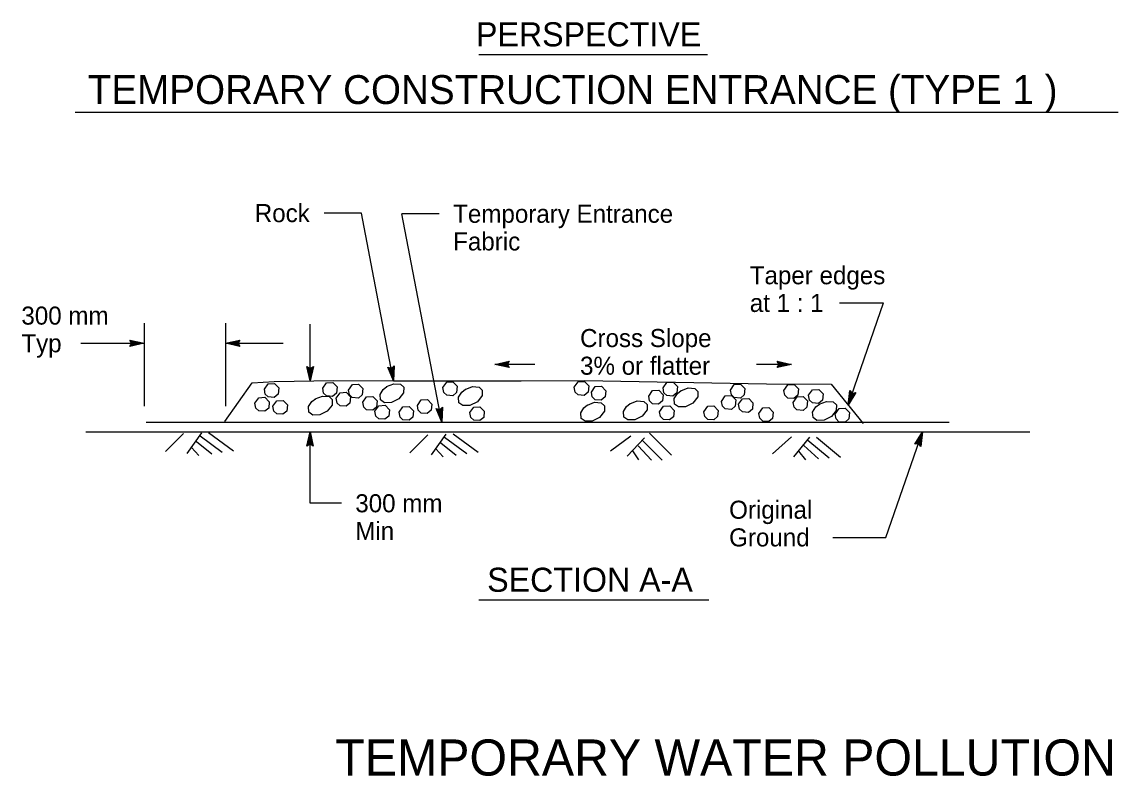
# Model space of a CAD drawing. Extents: x 6707406 to 6714471, y 1868570 to 1872341.
# Drawn here: x 6710442.3 to 6710879.6, y 1869895.8 to 1870196.5 of the extents above; entities that cross this region are included whole.
import ezdxf

# ---------------------------------------------------------------- set-up
doc = ezdxf.new("R2010")
doc.units = 0
for name, color, linetype in [('10 Sheet Formats', 7, 'Continuous'), ('56 Stg 3 Anno', 7, 'Continuous'), ('57 Undefined', 7, 'Continuous'), ('59 Soundwall Ann', 7, 'Continuous'), ('60 Nongeo Data', 7, 'Continuous')]:
    doc.layers.add(name, color=color, linetype=linetype)

msp = doc.modelspace()

# ---------------------------------------------------------------- linework, layer by layer
at = {"layer": '56 Stg 3 Anno'}
for p, q in [((6710577.77, 1870120.29), (6710562.94, 1870120.29)), ((6710590.62, 1870053.41), (6710577.77, 1870120.29)), ((6710609.91, 1870036.94), (6710593.95, 1870120.03)), ((6710608.78, 1870120.03), (6710593.95, 1870120.03)), ((6710768.54, 1870084.46), (6710786.08, 1870084.46)), ((6710771.94, 1870043.7), (6710786.08, 1870084.46)), ((6710491.13, 1870076.42), (6710491.13, 1870043.28)), ((6710523.55, 1870076.42), (6710523.55, 1870043.28)), ((6710557.31, 1870053.34), (6710557.31, 1870076.04)), ((6710465.81, 1870068.37), (6710491.13, 1870068.37)), ((6710486.14, 1870068.37), (6710485.37, 1870069.66)), ((6710485.37, 1870069.66), (6710485.37, 1870069.66)), ((6710485.37, 1870069.66), (6710491.13, 1870068.37)), ((6710491.13, 1870068.37), (6710485.37, 1870067.09)), ((6710485.37, 1870067.09), (6710486.14, 1870068.37)), ((6710485.37, 1870067.09), (6710485.37, 1870067.09)), ((6710485.58, 1870069.31), (6710489.8, 1870068.37)), ((6710489.79, 1870068.37), (6710485.59, 1870067.44)), ((6710488.48, 1870068.37), (6710485.76, 1870067.77)), ((6710485.8, 1870068.97), (6710488.48, 1870068.37)), ((6710485.97, 1870068.64), (6710487.15, 1870068.37)), ((6710487.15, 1870068.37), (6710485.99, 1870068.12)), ((6710491.13, 1870068.37), (6710491.13, 1870068.37)), ((6710523.55, 1870068.37), (6710529.31, 1870069.65)), ((6710523.55, 1870068.37), (6710546.59, 1870068.37)), ((6710529.31, 1870067.08), (6710523.55, 1870068.37)), ((6710523.55, 1870068.37), (6710523.55, 1870068.37)), ((6710529.1, 1870067.42), (6710524.87, 1870068.37)), ((6710524.88, 1870068.37), (6710529.08, 1870069.3)), ((6710526.2, 1870068.37), (6710528.91, 1870068.97)), ((6710528.88, 1870067.77), (6710526.2, 1870068.37)), ((6710527.53, 1870068.37), (6710528.69, 1870068.62)), ((6710528.71, 1870068.1), (6710527.53, 1870068.37)), ((6710529.31, 1870069.65), (6710528.54, 1870068.37)), ((6710528.54, 1870068.37), (6710529.31, 1870067.08)), ((6710529.31, 1870069.65), (6710529.31, 1870069.65)), ((6710529.31, 1870067.08), (6710529.31, 1870067.08)), ((6710557.31, 1870053.34), (6710556.03, 1870059.1)), ((6710556.03, 1870059.1), (6710556.03, 1870059.1)), ((6710556.03, 1870059.1), (6710557.31, 1870058.33)), ((6710557.31, 1870054.68), (6710556.38, 1870058.87)), ((6710557.31, 1870055.99), (6710556.71, 1870058.7)), ((6710557.31, 1870057.32), (6710557.06, 1870058.48)), ((6710557.31, 1870058.33), (6710558.6, 1870059.1)), ((6710558.6, 1870059.1), (6710557.31, 1870053.34)), ((6710558.26, 1870058.89), (6710557.31, 1870054.66)), ((6710557.91, 1870058.67), (6710557.31, 1870055.99)), ((6710557.58, 1870058.5), (6710557.31, 1870057.32)), ((6710558.6, 1870059.1), (6710558.6, 1870059.1)), ((6710590.62, 1870053.41), (6710588.28, 1870058.82)), ((6710588.28, 1870058.82), (6710588.28, 1870058.82)), ((6710588.28, 1870058.82), (6710589.68, 1870058.31)), ((6710590.37, 1870054.72), (6710588.66, 1870058.67)), ((6710590.12, 1870056.01), (6710589.02, 1870058.56)), ((6710589.87, 1870057.31), (6710589.4, 1870058.41)), ((6710589.68, 1870058.31), (6710590.8, 1870059.31)), ((6710589.91, 1870058.52), (6710589.87, 1870057.31)), ((6710590.21, 1870058.75), (6710590.12, 1870056.01)), ((6710590.5, 1870059.04), (6710590.37, 1870054.71)), ((6710590.8, 1870059.31), (6710590.62, 1870053.41)), ((6710590.8, 1870059.31), (6710590.8, 1870059.31)), ((6710631.02, 1870059.97), (6710636.78, 1870061.24)), ((6710646.98, 1870059.97), (6710631.02, 1870059.97)), ((6710636.78, 1870058.68), (6710631.02, 1870059.97)), ((6710631.02, 1870059.97), (6710631.02, 1870059.97)), ((6710636.57, 1870059.02), (6710632.34, 1870059.97)), ((6710632.35, 1870059.97), (6710636.55, 1870060.9)), ((6710633.67, 1870059.96), (6710636.38, 1870060.57)), ((6710636.34, 1870059.37), (6710633.67, 1870059.96)), ((6710634.99, 1870059.96), (6710636.15, 1870060.22)), ((6710636.17, 1870059.7), (6710634.99, 1870059.96)), ((6710636.78, 1870061.24), (6710636.01, 1870059.97)), ((6710636.01, 1870059.97), (6710636.78, 1870058.68)), ((6710636.78, 1870061.24), (6710636.78, 1870061.24)), ((6710636.78, 1870058.68), (6710636.78, 1870058.68)), ((6710749.39, 1870059.97), (6710735.38, 1870059.97)), ((6710744.4, 1870059.97), (6710743.63, 1870061.25)), ((6710743.63, 1870061.25), (6710743.63, 1870061.25)), ((6710743.63, 1870061.25), (6710749.39, 1870059.97)), ((6710749.39, 1870059.97), (6710743.63, 1870058.69)), ((6710743.63, 1870058.69), (6710744.4, 1870059.97)), ((6710743.63, 1870058.69), (6710743.63, 1870058.69)), ((6710743.84, 1870060.91), (6710748.07, 1870059.97)), ((6710748.06, 1870059.96), (6710743.86, 1870059.03)), ((6710746.74, 1870059.97), (6710744.03, 1870059.37)), ((6710744.07, 1870060.57), (6710746.74, 1870059.97)), ((6710744.24, 1870060.23), (6710745.42, 1870059.97)), ((6710745.42, 1870059.97), (6710744.26, 1870059.71)), ((6710749.39, 1870059.97), (6710749.39, 1870059.97)), ((6710557.31, 1870053.34), (6710557.31, 1870053.34)), ((6710590.62, 1870053.41), (6710590.62, 1870053.41)), ((6710771.94, 1870043.7), (6710772.62, 1870049.56)), ((6710775.04, 1870048.72), (6710771.94, 1870043.7)), ((6710772.37, 1870044.96), (6710772.87, 1870049.23)), ((6710774.65, 1870048.63), (6710772.37, 1870044.95)), ((6710772.62, 1870049.56), (6710772.62, 1870049.56)), ((6710772.62, 1870049.56), (6710773.58, 1870048.41)), ((6710772.81, 1870046.2), (6710773.13, 1870048.96)), ((6710774.25, 1870048.53), (6710772.81, 1870046.2)), ((6710773.25, 1870047.45), (6710773.38, 1870048.63)), ((6710773.88, 1870048.48), (6710773.25, 1870047.45)), ((6710773.58, 1870048.41), (6710775.04, 1870048.72)), ((6710775.04, 1870048.72), (6710775.04, 1870048.72)), ((6710609.91, 1870036.94), (6710607.57, 1870042.35)), ((6710607.57, 1870042.35), (6710607.57, 1870042.35)), ((6710607.57, 1870042.35), (6710608.97, 1870041.84)), ((6710609.66, 1870038.25), (6710607.96, 1870042.2)), ((6710609.42, 1870039.54), (6710608.31, 1870042.09)), ((6710609.17, 1870040.84), (6710608.7, 1870041.93)), ((6710608.97, 1870041.84), (6710610.09, 1870042.84)), ((6710609.2, 1870042.05), (6710609.17, 1870040.84)), ((6710609.5, 1870042.28), (6710609.42, 1870039.54)), ((6710609.8, 1870042.57), (6710609.67, 1870038.24)), ((6710610.09, 1870042.84), (6710609.91, 1870036.94)), ((6710610.09, 1870042.84), (6710610.09, 1870042.84)), ((6710771.94, 1870043.7), (6710771.94, 1870043.7)), ((6710609.91, 1870036.94), (6710609.91, 1870036.94)), ((6710556.03, 1870027.33), (6710557.31, 1870033.09)), ((6710556.37, 1870027.54), (6710557.31, 1870031.77)), ((6710557.31, 1870004.56), (6710557.31, 1870033.09)), ((6710557.31, 1870033.09), (6710557.31, 1870033.09)), ((6710557.31, 1870033.09), (6710558.59, 1870027.33)), ((6710557.31, 1870031.76), (6710558.24, 1870027.56)), ((6710787.05, 1869990.95), (6710801.67, 1870033.11)), ((6710798.57, 1870028.09), (6710801.67, 1870033.11)), ((6710798.96, 1870028.17), (6710801.24, 1870031.86)), ((6710801.24, 1870031.84), (6710800.74, 1870027.57)), ((6710801.67, 1870033.11), (6710800.99, 1870027.25)), ((6710801.67, 1870033.11), (6710801.67, 1870033.11)), ((6710557.31, 1870028.1), (6710556.03, 1870027.33)), ((6710556.03, 1870027.33), (6710556.03, 1870027.33)), ((6710556.71, 1870027.77), (6710557.31, 1870030.44)), ((6710557.04, 1870027.93), (6710557.31, 1870029.11)), ((6710557.31, 1870030.44), (6710557.91, 1870027.73)), ((6710557.31, 1870029.11), (6710557.57, 1870027.95)), ((6710558.59, 1870027.33), (6710557.31, 1870028.1)), ((6710558.59, 1870027.33), (6710558.59, 1870027.33)), ((6710800.04, 1870028.39), (6710798.57, 1870028.09)), ((6710798.57, 1870028.09), (6710798.57, 1870028.09)), ((6710799.36, 1870028.27), (6710800.8, 1870030.6)), ((6710799.73, 1870028.32), (6710800.37, 1870029.35)), ((6710800.99, 1870027.25), (6710800.04, 1870028.39)), ((6710800.37, 1870029.35), (6710800.23, 1870028.17)), ((6710800.8, 1870030.6), (6710800.48, 1870027.84)), ((6710800.99, 1870027.25), (6710800.99, 1870027.25)), ((6710569.84, 1870004.56), (6710557.31, 1870004.56)), ((6710765.86, 1869990.95), (6710787.05, 1869990.95))]:
    msp.add_line(p, q, dxfattribs=at)
at = {"layer": '57 Undefined'}
for p, q in [((6710624.62, 1870183.57), (6710715.9, 1870183.57)), ((6710463.58, 1870160.57), (6710879.64, 1870160.57)), ((6710624.57, 1869966.04), (6710716.36, 1869966.04))]:
    msp.add_line(p, q, dxfattribs=at)
at = {"layer": '59 Soundwall Ann'}
for p, q in [((6710506.78, 1870032.33), (6710499.61, 1870025.22)), ((6710513.93, 1870032.67), (6710508.15, 1870024.43)), ((6710513.39, 1870031.45), (6710522.28, 1870024.9)), ((6710516.84, 1870032.8), (6710526.79, 1870025.47)), ((6710604.29, 1870031.82), (6710597.12, 1870024.7)), ((6710611.44, 1870032.16), (6710605.66, 1870023.91)), ((6710610.89, 1870030.94), (6710619.79, 1870024.39)), ((6710614.34, 1870032.28), (6710624.3, 1870024.96)), ((6710685.24, 1870031.37), (6710677.11, 1870025.37)), ((6710690.68, 1870030.67), (6710683.76, 1870023.35)), ((6710692.73, 1870032.48), (6710701.51, 1870023.78)), ((6710749.31, 1870031), (6710741.73, 1870024.33)), ((6710756.47, 1870030.92), (6710750.21, 1870023.03)), ((6710759.38, 1870030.87), (6710768.87, 1870022.96)), ((6710510.01, 1870026.8), (6710512.91, 1870023.61)), ((6710511.95, 1870029.19), (6710518.05, 1870024.21)), ((6710609.45, 1870028.67), (6710615.56, 1870023.69)), ((6710688.21, 1870027.51), (6710693.52, 1870021.7)), ((6710689.96, 1870029.54), (6710697.81, 1870021.77)), ((6710754.28, 1870027.55), (6710760.08, 1870022.22)), ((6710755.85, 1870029.73), (6710764.34, 1870022.66)), ((6710607.51, 1870026.29), (6710610.42, 1870023.09)), ((6710685.94, 1870025.43), (6710688.35, 1870021.85)), ((6710752.2, 1870025.29), (6710754.91, 1870021.93))]:
    msp.add_line(p, q, dxfattribs=at)
at = {"layer": '60 Nongeo Data'}
for p, q in [((6710491.88, 1870036.94), (6710638.48, 1870036.94)), ((6710638.48, 1870036.94), (6710812.22, 1870036.94)), ((6710467.82, 1870033.11), (6710637.9, 1870033.11)), ((6710637.9, 1870033.11), (6710844.47, 1870033.11))]:
    msp.add_line(p, q, dxfattribs=at)
for points in [[(6710523.29, 1870037.15), (6710534.22, 1870052.61), (6710543, 1870053.06), (6710566.73, 1870053.52), (6710590.57, 1870053.41), (6710641.46, 1870053.45)], [(6710562.32, 1870050.4), (6710563.87, 1870052.6), (6710566.34, 1870052.74), (6710568.06, 1870050.96), (6710567.81, 1870048.46), (6710566.28, 1870047.19), (6710563.84, 1870047.37), (6710562.69, 1870048.48), (6710562.32, 1870050.4)], [(6710610.27, 1870050.67), (6710611.82, 1870052.87), (6710614.3, 1870053.01), (6710616.02, 1870051.23), (6710615.77, 1870048.73), (6710614.24, 1870047.46), (6710611.8, 1870047.64), (6710610.65, 1870048.75), (6710610.27, 1870050.67)], [(6710641.46, 1870053.45), (6710666.79, 1870053.47), (6710739.37, 1870052.21), (6710765.14, 1870052.09), (6710777.89, 1870036.35)], [(6710662.71, 1870050.8), (6710664.26, 1870053), (6710666.73, 1870053.15), (6710668.45, 1870051.36), (6710668.2, 1870048.86), (6710666.68, 1870047.59), (6710664.23, 1870047.77), (6710663.08, 1870048.88), (6710662.71, 1870050.8)], [(6710698.1, 1870050.55), (6710699.65, 1870052.75), (6710702.12, 1870052.89), (6710703.84, 1870051.11), (6710703.59, 1870048.61), (6710702.07, 1870047.34), (6710699.62, 1870047.51), (6710698.47, 1870048.63), (6710698.1, 1870050.55)], [(6710539.06, 1870050.02), (6710540.61, 1870052.23), (6710543.09, 1870052.37), (6710544.8, 1870050.59), (6710544.56, 1870048.08), (6710543.03, 1870046.81), (6710540.58, 1870046.99), (6710539.43, 1870048.11), (6710539.06, 1870050.02)], [(6710567.72, 1870046.47), (6710569.27, 1870048.67), (6710571.75, 1870048.81), (6710573.47, 1870047.03), (6710573.22, 1870044.53), (6710571.69, 1870043.26), (6710569.25, 1870043.44), (6710568.1, 1870044.55), (6710567.73, 1870046.47)], [(6710572.61, 1870049.73), (6710574.16, 1870051.94), (6710576.64, 1870052.08), (6710578.36, 1870050.29), (6710578.11, 1870047.79), (6710576.58, 1870046.52), (6710574.14, 1870046.7), (6710572.99, 1870047.81), (6710572.62, 1870049.73)], [(6710587.83, 1870051.08), (6710590.73, 1870052.23), (6710593.4, 1870052), (6710594.66, 1870050.8), (6710594.62, 1870048.63), (6710592.7, 1870046.18), (6710589.73, 1870044.69), (6710586.93, 1870044.64), (6710585.36, 1870045.76), (6710585.21, 1870047.99), (6710586.48, 1870049.99), (6710587.95, 1870051.15)], [(6710619.17, 1870049.97), (6710622.07, 1870051.12), (6710624.74, 1870050.89), (6710626, 1870049.69), (6710625.96, 1870047.53), (6710624.04, 1870045.07), (6710621.07, 1870043.59), (6710618.27, 1870043.54), (6710616.7, 1870044.66), (6710616.55, 1870046.89), (6710617.83, 1870048.88), (6710619.29, 1870050.05)], [(6710669.5, 1870048.89), (6710671.05, 1870051.09), (6710673.52, 1870051.23), (6710675.24, 1870049.45), (6710674.99, 1870046.95), (6710673.46, 1870045.68), (6710671.02, 1870045.86), (6710669.87, 1870046.97), (6710669.5, 1870048.89)], [(6710692.39, 1870047.28), (6710693.94, 1870049.49), (6710696.42, 1870049.63), (6710698.14, 1870047.85), (6710697.89, 1870045.35), (6710696.36, 1870044.07), (6710693.92, 1870044.25), (6710692.77, 1870045.37), (6710692.4, 1870047.28)], [(6710705.17, 1870049.45), (6710708.07, 1870050.6), (6710710.73, 1870050.37), (6710712, 1870049.16), (6710711.96, 1870047), (6710710.03, 1870044.55), (6710707.06, 1870043.06), (6710704.27, 1870043.01), (6710702.69, 1870044.13), (6710702.54, 1870046.36), (6710703.82, 1870048.36), (6710705.28, 1870049.52)], [(6710724.99, 1870049.73), (6710726.54, 1870051.94), (6710729.01, 1870052.08), (6710730.73, 1870050.29), (6710730.48, 1870047.79), (6710728.95, 1870046.52), (6710726.51, 1870046.7), (6710725.36, 1870047.81), (6710724.99, 1870049.73)], [(6710746.34, 1870049.58), (6710747.89, 1870051.78), (6710750.36, 1870051.92), (6710752.08, 1870050.14), (6710751.84, 1870047.64), (6710750.31, 1870046.37), (6710747.86, 1870046.54), (6710746.71, 1870047.66), (6710746.34, 1870049.57)], [(6710756.18, 1870047.62), (6710757.73, 1870049.82), (6710760.2, 1870049.96), (6710761.92, 1870048.18), (6710761.67, 1870045.68), (6710760.14, 1870044.41), (6710757.7, 1870044.59), (6710756.55, 1870045.7), (6710756.18, 1870047.62)], [(6710535.28, 1870044.47), (6710536.84, 1870046.67), (6710539.31, 1870046.82), (6710541.03, 1870045.03), (6710540.78, 1870042.53), (6710539.25, 1870041.26), (6710536.81, 1870041.44), (6710535.66, 1870042.55), (6710535.29, 1870044.47)], [(6710542.5, 1870043.25), (6710544.05, 1870045.45), (6710546.53, 1870045.59), (6710548.25, 1870043.81), (6710548, 1870041.31), (6710546.47, 1870040.04), (6710544.02, 1870040.22), (6710542.87, 1870041.33), (6710542.5, 1870043.25)], [(6710559.31, 1870046.19), (6710562.21, 1870047.34), (6710564.88, 1870047.11), (6710566.14, 1870045.9), (6710566.1, 1870043.74), (6710564.18, 1870041.29), (6710561.21, 1870039.8), (6710558.41, 1870039.75), (6710556.84, 1870040.87), (6710556.69, 1870043.1), (6710557.97, 1870045.09), (6710559.43, 1870046.26)], [(6710578.32, 1870044.84), (6710579.87, 1870047.04), (6710582.34, 1870047.18), (6710584.06, 1870045.4), (6710583.81, 1870042.9), (6710582.29, 1870041.63), (6710579.84, 1870041.81), (6710578.69, 1870042.92), (6710578.32, 1870044.84)], [(6710600.11, 1870043.58), (6710601.66, 1870045.79), (6710604.13, 1870045.93), (6710605.85, 1870044.14), (6710605.6, 1870041.64), (6710604.07, 1870040.37), (6710601.63, 1870040.55), (6710600.48, 1870041.66), (6710600.11, 1870043.58)], [(6710667.92, 1870043.68), (6710670.82, 1870044.83), (6710673.48, 1870044.6), (6710674.75, 1870043.4), (6710674.71, 1870041.23), (6710672.78, 1870038.78), (6710669.81, 1870037.29), (6710667.02, 1870037.24), (6710665.44, 1870038.36), (6710665.29, 1870040.59), (6710666.57, 1870042.59), (6710668.03, 1870043.76)], [(6710684.92, 1870044.25), (6710687.82, 1870045.4), (6710690.49, 1870045.17), (6710691.75, 1870043.96), (6710691.71, 1870041.8), (6710689.79, 1870039.35), (6710686.82, 1870037.86), (6710684.02, 1870037.81), (6710682.45, 1870038.93), (6710682.3, 1870041.16), (6710683.58, 1870043.15), (6710685.04, 1870044.32)], [(6710721.39, 1870045.21), (6710722.95, 1870047.41), (6710725.42, 1870047.56), (6710727.14, 1870045.77), (6710726.89, 1870043.27), (6710725.36, 1870042), (6710722.92, 1870042.18), (6710721.77, 1870043.29), (6710721.4, 1870045.21)], [(6710728.25, 1870044.02), (6710729.8, 1870046.23), (6710732.27, 1870046.37), (6710733.99, 1870044.59), (6710733.74, 1870042.08), (6710732.21, 1870040.81), (6710729.77, 1870040.99), (6710728.62, 1870042.1), (6710728.25, 1870044.02)], [(6710750, 1870044.8), (6710751.55, 1870047), (6710754.03, 1870047.15), (6710755.75, 1870045.36), (6710755.5, 1870042.86), (6710753.97, 1870041.59), (6710751.53, 1870041.77), (6710750.38, 1870042.88), (6710750, 1870044.8)], [(6710760.42, 1870044.05), (6710763.32, 1870045.2), (6710765.98, 1870044.97), (6710767.25, 1870043.76), (6710767.21, 1870041.6), (6710765.29, 1870039.15), (6710762.32, 1870037.66), (6710759.52, 1870037.61), (6710757.94, 1870038.73), (6710757.79, 1870040.96), (6710759.07, 1870042.96), (6710760.54, 1870044.12)], [(6710583.17, 1870041.28), (6710584.72, 1870043.48), (6710587.2, 1870043.62), (6710588.92, 1870041.84), (6710588.67, 1870039.34), (6710587.14, 1870038.07), (6710584.7, 1870038.25), (6710583.55, 1870039.36), (6710583.17, 1870041.28)], [(6710592.81, 1870040.85), (6710594.36, 1870043.05), (6710596.84, 1870043.19), (6710598.56, 1870041.41), (6710598.31, 1870038.91), (6710596.78, 1870037.64), (6710594.33, 1870037.81), (6710593.18, 1870038.93), (6710592.81, 1870040.84)], [(6710621.05, 1870040.73), (6710622.6, 1870042.93), (6710625.08, 1870043.07), (6710626.8, 1870041.29), (6710626.55, 1870038.79), (6710625.02, 1870037.52), (6710622.57, 1870037.69), (6710621.43, 1870038.81), (6710621.05, 1870040.72)], [(6710696.75, 1870041.03), (6710698.3, 1870043.24), (6710700.78, 1870043.38), (6710702.5, 1870041.59), (6710702.25, 1870039.09), (6710700.72, 1870037.82), (6710698.28, 1870038), (6710697.13, 1870039.12), (6710696.75, 1870041.03)], [(6710714.39, 1870041.06), (6710715.94, 1870043.26), (6710718.42, 1870043.41), (6710720.14, 1870041.62), (6710719.89, 1870039.12), (6710718.36, 1870037.85), (6710715.91, 1870038.03), (6710714.76, 1870039.14), (6710714.39, 1870041.06)], [(6710736.34, 1870040.36), (6710737.89, 1870042.56), (6710740.36, 1870042.71), (6710742.08, 1870040.92), (6710741.83, 1870038.42), (6710740.3, 1870037.15), (6710737.86, 1870037.33), (6710736.71, 1870038.44), (6710736.34, 1870040.36)], [(6710766.76, 1870040.14), (6710768.31, 1870042.34), (6710770.79, 1870042.48), (6710772.51, 1870040.7), (6710772.26, 1870038.2), (6710770.73, 1870036.93), (6710768.29, 1870037.1), (6710767.14, 1870038.22), (6710766.76, 1870040.13)]]:
    msp.add_lwpolyline(points, dxfattribs=at)

# ---------------------------------------------------------------- texts
at = {"layer": '10 Sheet Formats'}
msp.add_text('TEMPORARY WATER POLLUTION', height=14.4003, dxfattribs=at).set_placement((6710567.39, 1869895.96))
at = {"layer": '57 Undefined'}
for s, height, p in [('PERSPECTIVE', 9.6002, (6710623.48, 1870186.79)), ('TEMPORARY CONSTRUCTION ENTRANCE (TYPE 1 )', 11.5203, (6710468.61, 1870163.79)), ('Rock', 7.2, (6710535.24, 1870116.69)), ('Temporary Entrance', 7.2002, (6710614.38, 1870116.43)), ('Fabric', 7.2, (6710614.38, 1870105.39)), ('Taper edges', 7.2002, (6710732.71, 1870091.9)), ('at 1 : 1', 7.2, (6710732.71, 1870080.86)), ('300 mm', 7.2, (6710442.13, 1870075.81)), ('Cross Slope', 7.2002, (6710665.01, 1870066.86)), ('Typ', 7.2, (6710442.13, 1870064.77)), ('3% or flatter', 7.2002, (6710665.01, 1870055.82)), ('300 mm', 7.2, (6710575.34, 1870000.96)), ('Original', 7.2, (6710724.47, 1869998.39)), ('Min', 7.2, (6710575.34, 1869989.92)), ('Ground', 7.2, (6710724.47, 1869987.35)), ('SECTION A-A', 9.6002, (6710627.96, 1869969.26))]:
    msp.add_text(s, height=height, dxfattribs=at).set_placement(p)

doc.saveas('drawing.dxf')
